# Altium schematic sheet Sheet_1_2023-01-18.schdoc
size 238 x 129 mm
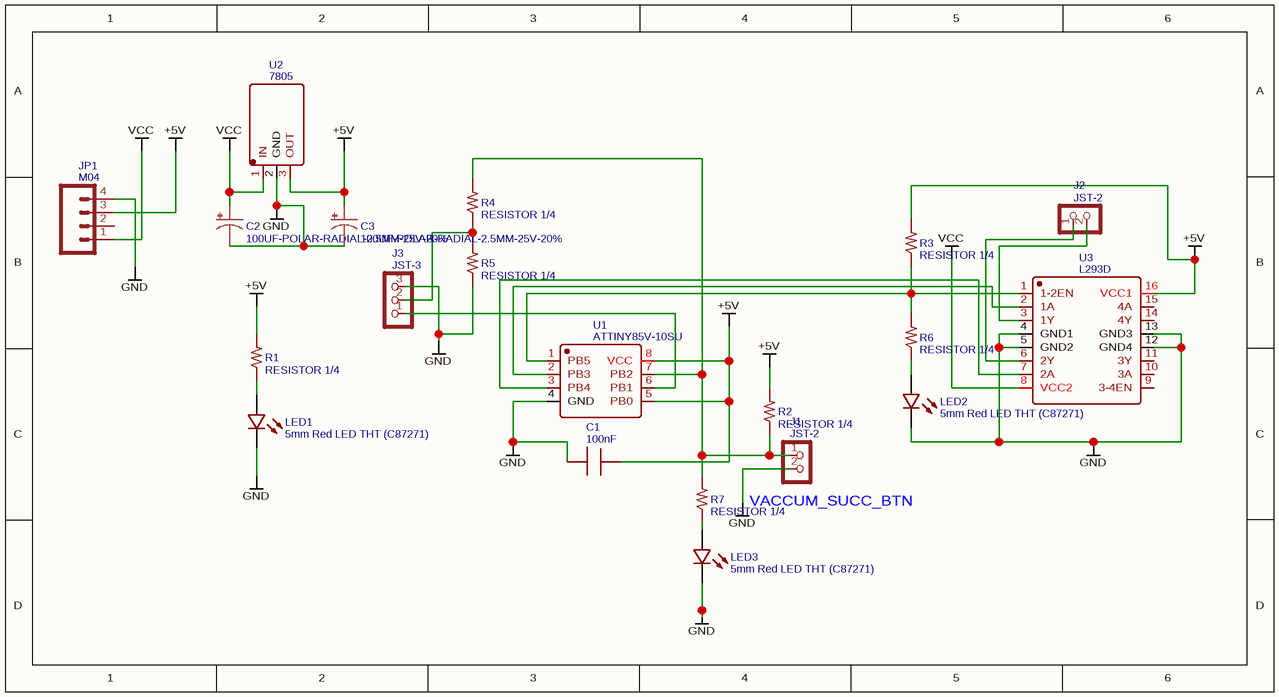
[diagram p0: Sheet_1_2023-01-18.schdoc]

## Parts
C1  100nF  [RAD-0.2]
C2  100UF-POLAR-RADIAL-2.5MM-25V-20%  [CPOL-RADIAL-2.5MM-6.5MM]
C3  100UF-POLAR-RADIAL-2.5MM-25V-20%  [CPOL-RADIAL-2.5MM-6.5MM]
J1  JST-2  [JST-2]
J2  JST-2  [JST-2]
J3  JST-3  [JST-3]
JP1  M04  [SCREWTERMINAL-3.5MM-4]
LED1  5mm Red LED THT (C87271)  [LED-5MM-2.54MM]
LED2  5mm Red LED THT (C87271)  [LED-5MM-2.54MM]
LED3  5mm Red LED THT (C87271)  [LED-5MM-2.54MM]
R1  RESISTOR 1/4  [AXIAL 1/4]
R2  RESISTOR 1/4  [AXIAL 1/4]
R3  RESISTOR 1/4  [AXIAL 1/4]
R4  RESISTOR 1/4  [AXIAL 1/4]
R5  RESISTOR 1/4  [AXIAL 1/4]
R6  RESISTOR 1/4  [AXIAL 1/4]
R7  RESISTOR 1/4  [AXIAL 1/4]
U1  ATTINY85V-10SU  [SOIC-8_208MIL]
U2  7805  [TO-220]
U3  L293D  [DIP16]

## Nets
+5V: C1.1 C3.1(+) JP1.3 R1.2 R2.2 R3.2 U1.5(PB0) U1.8(VCC) U2.3(OUT) U3.16(VCC1)
GND: C1.2 C2.2(-) C3.2(-) J1.2 J3.3 JP1.4 LED1.2(C) LED2.2(C) LED3.2(C) R5.1 U1.4(GND) U2.2(GND) U3.4(GND1) U3.5(GND2) U3.12(GND4) U3.13(GND3)
VCC: C2.1(+) JP1.1 U2.1(IN) U3.8(VCC2)
NetJ1_1: J1.1 R2.1 R4.2 R7.2 U1.7(PB2)
NetJ2_1: J2.1 U3.6(2Y)
NetJ2_2: J2.2 U3.3(1Y)
NetJ3_1: J3.1 U1.6(PB1)
NetJ3_2: J3.2 R4.1 R5.2
NetLED1_1: LED1.1(A) R1.1
NetLED2_1: LED2.1(A) R6.1
NetLED3_1: LED3.1(A) R7.1
NetR3_1: R3.1 R6.2 U1.1(PB5) U3.1(1-2EN)
NetU1_2: U1.2(PB3) U3.2(1A)
NetU1_3: U1.3(PB4) U3.7(2A)

Not connected (* = marked no-connect by the designer): JP1 2; U3 9(3-4EN) 10(3A) 11(3Y) 14(4Y) 15(4A)

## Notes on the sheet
- (near J1) VACCUM_SUCC_BTN

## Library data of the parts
C1 = 100nF: BOM_Manufacturer: EasyEDA; BOM_Manufacturer Part: 104/100V 20%; Voltage: 400V; Tolerance: ±10%; BOM_EasyEDA: C26856
C2 C3 = 100UF-POLAR-RADIAL-2.5MM-25V-20%: Contributor: sagedot
J1 J2 = JST-2: Contributor: cpu76239
J3 = JST-3: Contributor: cpu76239
JP1 = M04: Contributor: SparkFun
LED1-LED3 = 5mm Red LED THT (C87271): BOM_Manufacturer: EVERLIGHT; BOM_Manufacturer Part: 333-2SURD/S530-A3
R1-R7 = RESISTOR 1/4: Contributor: fmava
U1 = ATTINY85V-10SU: BOM_Manufacturer: Microchip Tech; Contributor: LCSC
U2 = 7805: BOM_Manufacturer: Foshan Blue Rocket Elec; Contributor: LCSC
